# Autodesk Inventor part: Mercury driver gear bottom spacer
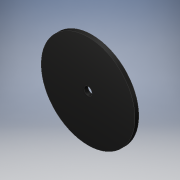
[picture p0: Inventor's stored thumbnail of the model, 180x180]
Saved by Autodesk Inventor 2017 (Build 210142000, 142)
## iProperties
Created: 2016-07
Part Number: Mercury driver gear bottom spacer
Material: Generic
Document SubType Name: Modeling
Designer: Stan
Density: 1 g/cm^3
Appearance: Glossy - Black
Author: Stan
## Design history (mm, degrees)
sketch "Sketch1"
  geometry: C1 r 38.1 at (0, 0); C2 r 3.302 at (0, 0); 1 further point
  constraints: 2 centre point, 2 coincident
  dimensions: "d0" = 76.2 diameter of C1; "d1" = 6.604 diameter of C2
extrude "Extrusion1" new body sketch "Sketch1" distance "d2" = 3.175; taper "d3" = 0 deg
body "Solid1"
